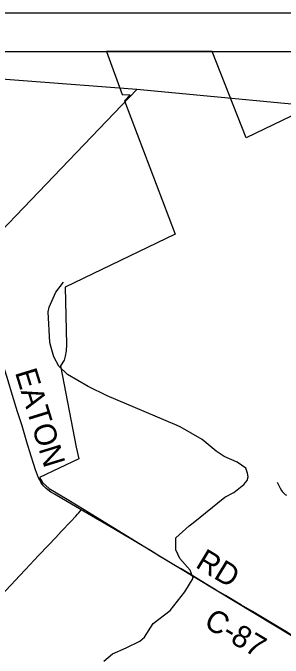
# Model space of a CAD drawing. Extents: x -19.5 to 44.1, y 0 to 22.
# Drawn here: x -15.579 to -14.882, y 19.332 to 21 of the extents above; entities that cross this region are included whole.
import ezdxf

# ---------------------------------------------------------------- set-up
doc = ezdxf.new("R2010")
doc.units = 0
for name, color, linetype in [('GM_X_City_Street', 7, 'Continuous'), ('GM_X_Corporation', 7, 'Continuous'), ('GM_X_County_Road', 7, 'Continuous'), ('GM_X_County_Road_Text', 7, 'Continuous'), ('GM_X_Minor_River', 7, 'Continuous'), ('GM_X_Township', 7, 'Continuous'), ('GM_X_Township_Road', 7, 'Continuous'), ('SH_Data', 7, 'Continuous')]:
    doc.layers.add(name, color=color, linetype=linetype)

msp = doc.modelspace()

# ---------------------------------------------------------------- linework, layer by layer
at = {"layer": 'GM_X_City_Street'}
msp.add_lwpolyline([(-14.8972, 19.7873), (-14.8895, 19.7711), (-14.8861, 19.7652), (-14.8847, 19.7631), (-14.8832, 19.7612), (-14.8813, 19.7592), (-14.8797, 19.7576), (-14.8769, 19.7553), (-14.8737, 19.753)], dxfattribs=at)
at = {"layer": 'GM_X_Corporation'}
msp.add_line((-15.0651, 20.9), (-15.3378, 20.9), dxfattribs=at)
for points in [[(-15.3378, 20.9), (-15.2971, 20.7893), (-15.2768, 20.7882), (-15.2911, 20.7729), (-15.1611, 20.4279), (-15.4442, 20.2906), (-15.4415, 20.1427), (-15.442, 20.1262), (-15.4442, 20.1124), (-15.4474, 20.1023), (-15.4569, 20.0879), (-15.416, 19.8772), (-15.409, 19.8469), (-15.5107, 19.799), (-15.5027, 19.7862), (-15.4857, 19.7703), (-15.4348, 19.7407), (-15.3956, 19.7164), (-15.2058, 19.5986), (-14.8562, 19.3878)], [(-14.691, 20.9), (-14.6625, 20.8286), (-14.7681, 20.7778), (-14.9779, 20.6772), (-15.0651, 20.9)]]:
    msp.add_lwpolyline(points, dxfattribs=at)
at = {"layer": 'GM_X_County_Road'}
for points in [[(-15.4031, 19.7154), (-15.4078, 19.7181), (-15.4384, 19.7359), (-15.4722, 19.7556), (-15.4818, 19.7614), (-15.4891, 19.7669), (-15.4944, 19.7714), (-15.4994, 19.7766), (-15.5041, 19.7821), (-15.5076, 19.7871), (-15.5102, 19.7918), (-15.5133, 19.7978), (-15.5164, 19.8053), (-15.5209, 19.8188), (-15.5261, 19.8354), (-15.5321, 19.854), (-15.5434, 19.8906), (-15.556, 19.9322), (-15.5673, 19.969), (-15.5801, 20.0112), (-15.5918, 20.0492), (-15.5997, 20.0741), (-15.6069, 20.0965)], [(-15.2043, 19.5977), (-15.2132, 19.6031), (-15.2245, 19.6098), (-15.2495, 19.6248), (-15.2751, 19.64), (-15.2869, 19.6469), (-15.3189, 19.6659), (-15.3868, 19.706), (-15.4031, 19.7154)], [(-14.8315, 19.3546), (-14.835, 19.3598), (-14.8475, 19.3775), (-14.8525, 19.3838), (-14.8562, 19.3878), (-14.8609, 19.3918), (-14.8653, 19.3951), (-14.8731, 19.4), (-14.8881, 19.4089), (-14.9613, 19.4523), (-14.9896, 19.4692), (-15.031, 19.4941), (-15.0545, 19.508), (-15.0833, 19.5253), (-15.1082, 19.5404), (-15.1236, 19.5497), (-15.1456, 19.5627), (-15.1638, 19.5731), (-15.1943, 19.5916), (-15.2043, 19.5977)]]:
    msp.add_lwpolyline(points, dxfattribs=at)
at = {"layer": 'GM_X_Minor_River'}
msp.add_lwpolyline([(-15.3448, 19.3242), (-15.3228, 19.3432), (-15.2876, 19.3589), (-15.2516, 19.3758), (-15.2401, 19.3858), (-15.2178, 19.4215), (-15.1736, 19.4553), (-15.1359, 19.5033), (-15.1144, 19.5386), (-15.1224, 19.5593), (-15.1489, 19.5893), (-15.1587, 19.6123), (-15.1593, 19.6431), (-15.125, 19.6736), (-15.1139, 19.6818), (-15.0322, 19.748), (-15.0089, 19.7605), (-14.9831, 19.7809), (-14.9753, 19.7911), (-14.9725, 19.8009), (-14.9738, 19.8104), (-14.9786, 19.823), (-15.0007, 19.839), (-15.0342, 19.8536), (-15.0549, 19.8669), (-15.0912, 19.8971), (-15.1476, 19.9296), (-15.1612, 19.9359), (-15.3361, 20.0103), (-15.385, 20.0339), (-15.4388, 20.0648), (-15.4612, 20.0869), (-15.4741, 20.1106), (-15.4805, 20.1347), (-15.4845, 20.148), (-15.4888, 20.2271), (-15.4863, 20.2392), (-15.4689, 20.2784), (-15.4487, 20.3043)], dxfattribs=at)
at = {"layer": 'GM_X_Township'}
for points in [[(-15.2593, 20.802), (-15.847, 20.8464), (-16.0007, 20.858), (-16.2716, 20.8785), (-16.5567, 20.9)], [(-14.6789, 20.7469), (-15.2593, 20.802), (-15.6886, 20.3541), (-16.051, 19.976), (-16.1044, 19.9156), (-17.0212, 18.964), (-17.1488, 18.8309), (-17.1646, 18.7784), (-17.2501, 18.4952), (-17.3561, 18.1443), (-17.4643, 17.7858)]]:
    msp.add_lwpolyline(points, dxfattribs=at)
at = {"layer": 'GM_X_Township_Road'}
msp.add_lwpolyline([(-15.6236, 19.4797), (-15.5732, 19.5337), (-15.5628, 19.5445), (-15.5471, 19.5612), (-15.5131, 19.5974), (-15.4879, 19.624), (-15.4691, 19.6439), (-15.4546, 19.6593), (-15.43, 19.6856), (-15.4175, 19.6986), (-15.4125, 19.7041), (-15.4101, 19.707), (-15.4058, 19.7122), (-15.4031, 19.7154)], dxfattribs=at)
at = {"layer": 'SH_Data'}
for p, q in [((-19.313, 21), (-12.313, 21)), ((-16.7391, 20.9), (-12.413, 20.9))]:
    msp.add_line(p, q, dxfattribs=at)

# ---------------------------------------------------------------- texts
at = {"layer": 'GM_X_County_Road_Text'}
for s, rotation, p in [('EATON', 287.1597, (-15.5746, 20.0708)), ('RD', 328.8658, (-15.111, 19.5685)), ('C-87', 329.1533, (-15.0898, 19.4151))]:
    msp.add_text(s, height=0.05682, rotation=rotation, dxfattribs=at).set_placement(p)

doc.saveas('drawing.dxf')
